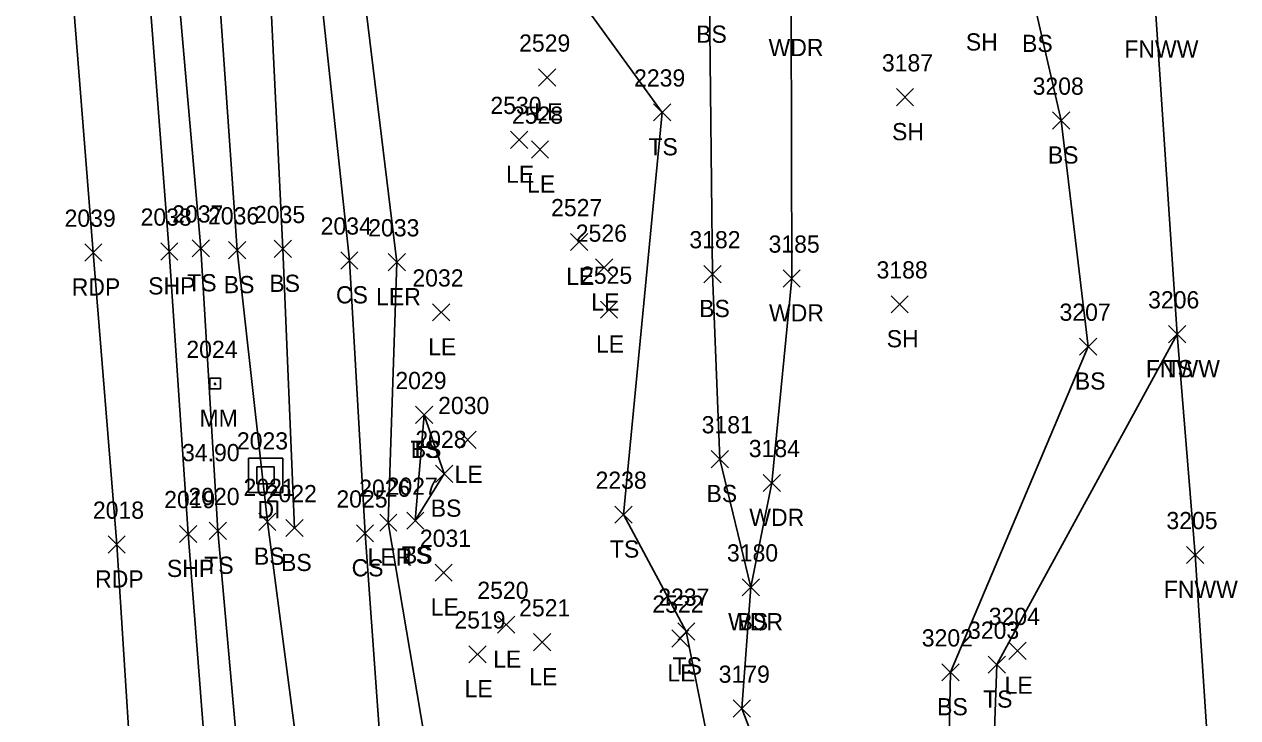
# Model space of a CAD drawing. Extents: x 1650221 to 1650634, y 244606 to 249996.
# Drawn here: x 1650407.2 to 1650548.3, y 245661.6 to 245742.3 of the extents above; entities that cross this region are included whole.
import ezdxf

# ---------------------------------------------------------------- set-up
doc = ezdxf.new("R2010")
doc.units = 0
for name, color, linetype in [('D_A', 7, 'Continuous'), ('D_I', 7, 'Continuous'), ('DS', 7, 'Continuous'), ('L_A', 7, 'Continuous'), ('L_I', 7, 'Continuous'), ('L_TIC', 7, 'Continuous'), ('LARO', 7, 'Continuous'), ('LAWA', 7, 'Continuous'), ('LELB', 7, 'Continuous'), ('LFNC', 7, 'Continuous'), ('LSOGP', 7, 'Continuous'), ('P_A', 7, 'Continuous'), ('P_I', 7, 'Continuous'), ('P_TIC', 7, 'Continuous'), ('PET', 7, 'Continuous'), ('PSP', 7, 'Continuous'), ('S_A', 7, 'Continuous'), ('S_C', 7, 'Continuous'), ('S_I', 7, 'Continuous'), ('SRM', 7, 'Continuous')]:
    doc.layers.add(name, color=color, linetype=linetype)

msp = doc.modelspace()

# ---------------------------------------------------------------- linework, layer by layer
at = {"layer": 'DS'}
for p, q in [((1650433.22, 245691.82), (1650437.22, 245691.82)), ((1650433.22, 245687.82), (1650433.22, 245691.82)), ((1650434.22, 245688.82), (1650434.22, 245690.82)), ((1650434.22, 245690.82), (1650436.22, 245690.82)), ((1650436.22, 245690.82), (1650436.22, 245688.82)), ((1650437.22, 245691.82), (1650437.22, 245687.82)), ((1650435.23, 245689.83), (1650435.23, 245689.83)), ((1650435.23, 245689.83), (1650435.23, 245689.83)), ((1650437.22, 245687.82), (1650433.22, 245687.82)), ((1650436.22, 245688.82), (1650434.22, 245688.82))]:
    msp.add_line(p, q, dxfattribs=at)
at = {"layer": 'L_TIC'}
for points in [[(1650466.98, 245735.08), (1650468.98, 245737.08)], [(1650468.98, 245735.08), (1650466.98, 245737.08)], [(1650508.59, 245732.78), (1650510.59, 245734.78)], [(1650510.59, 245732.78), (1650508.59, 245734.78)], [(1650480.34, 245731.02), (1650482.34, 245733.02)], [(1650482.34, 245731.02), (1650480.34, 245733.02)], [(1650526.76, 245730.07), (1650528.76, 245732.07)], [(1650528.76, 245730.07), (1650526.76, 245732.07)], [(1650463.72, 245727.83), (1650465.72, 245729.83)], [(1650465.72, 245727.83), (1650463.72, 245729.83)], [(1650466.14, 245726.7), (1650468.14, 245728.7)], [(1650468.14, 245726.7), (1650466.14, 245728.7)], [(1650470.69, 245715.95), (1650472.69, 245717.95)], [(1650472.69, 245715.95), (1650470.69, 245717.95)], [(1650426.7, 245715.21), (1650428.7, 245717.21)], [(1650428.7, 245715.21), (1650426.7, 245717.21)], [(1650430.92, 245715), (1650432.92, 245717)], [(1650432.92, 245715), (1650430.92, 245717)], [(1650436.22, 245715.15), (1650438.22, 245717.15)], [(1650438.22, 245715.15), (1650436.22, 245717.15)], [(1650443.97, 245713.81), (1650445.97, 245715.81)], [(1650445.97, 245713.81), (1650443.97, 245715.81)], [(1650449.49, 245713.6), (1650451.49, 245715.6)], [(1650451.49, 245713.6), (1650449.49, 245715.6)], [(1650473.61, 245712.98), (1650475.61, 245714.98)], [(1650475.61, 245712.98), (1650473.61, 245714.98)], [(1650486.21, 245712.22), (1650488.21, 245714.22)], [(1650488.21, 245712.22), (1650486.21, 245714.22)], [(1650495.41, 245711.71), (1650497.41, 245713.71)], [(1650497.41, 245711.71), (1650495.41, 245713.71)], [(1650507.97, 245708.71), (1650509.97, 245710.71)], [(1650509.97, 245708.71), (1650507.97, 245710.71)], [(1650454.64, 245707.77), (1650456.64, 245709.77)], [(1650456.64, 245707.77), (1650454.64, 245709.77)], [(1650474.17, 245708.09), (1650476.17, 245710.09)], [(1650476.17, 245708.09), (1650474.17, 245710.09)], [(1650540.25, 245705.23), (1650542.25, 245707.23)], [(1650542.25, 245705.23), (1650540.25, 245707.23)], [(1650540.25, 245705.23), (1650542.25, 245707.23)], [(1650542.25, 245705.23), (1650540.25, 245707.23)], [(1650529.9, 245703.79), (1650531.9, 245705.79)], [(1650531.9, 245703.79), (1650529.9, 245705.79)], [(1650452.67, 245695.85), (1650454.67, 245697.85)], [(1650454.67, 245695.85), (1650452.67, 245697.85)], [(1650452.67, 245695.85), (1650454.67, 245697.85)], [(1650454.67, 245695.85), (1650452.67, 245697.85)], [(1650457.72, 245692.95), (1650459.72, 245694.95)], [(1650459.72, 245692.95), (1650457.72, 245694.95)], [(1650487.06, 245690.71), (1650489.06, 245692.71)], [(1650489.06, 245690.71), (1650487.06, 245692.71)], [(1650454.99, 245689.01), (1650456.99, 245691.01)], [(1650456.99, 245689.01), (1650454.99, 245691.01)], [(1650493.11, 245687.94), (1650495.11, 245689.94)], [(1650495.11, 245687.94), (1650493.11, 245689.94)], [(1650475.86, 245684.26), (1650477.86, 245686.26)], [(1650477.86, 245684.26), (1650475.86, 245686.26)], [(1650434.43, 245683.43), (1650436.43, 245685.43)], [(1650436.43, 245683.43), (1650434.43, 245685.43)], [(1650448.5, 245683.33), (1650450.5, 245685.33)], [(1650450.5, 245683.33), (1650448.5, 245685.33)], [(1650451.64, 245683.56), (1650453.64, 245685.56)], [(1650453.64, 245683.56), (1650451.64, 245685.56)], [(1650451.64, 245683.56), (1650453.64, 245685.56)], [(1650453.64, 245683.56), (1650451.64, 245685.56)], [(1650428.68, 245682.37), (1650430.68, 245684.37)], [(1650430.68, 245682.37), (1650428.68, 245684.37)], [(1650437.58, 245682.7), (1650439.58, 245684.7)], [(1650439.58, 245682.7), (1650437.58, 245684.7)], [(1650445.79, 245682.08), (1650447.79, 245684.08)], [(1650447.79, 245682.08), (1650445.79, 245684.08)], [(1650542.33, 245679.57), (1650544.33, 245681.57)], [(1650544.33, 245679.57), (1650542.33, 245681.57)], [(1650454.94, 245677.51), (1650456.94, 245679.51)], [(1650456.94, 245677.51), (1650454.94, 245679.51)], [(1650490.66, 245675.81), (1650492.66, 245677.81)], [(1650492.66, 245675.81), (1650490.66, 245677.81)], [(1650490.66, 245675.81), (1650492.66, 245677.81)], [(1650492.66, 245675.81), (1650490.66, 245677.81)], [(1650462.2, 245671.46), (1650464.2, 245673.46)], [(1650464.2, 245671.46), (1650462.2, 245673.46)], [(1650483.15, 245670.67), (1650485.15, 245672.67)], [(1650485.15, 245670.67), (1650483.15, 245672.67)], [(1650466.4, 245669.43), (1650468.4, 245671.43)], [(1650468.4, 245669.43), (1650466.4, 245671.43)], [(1650482.46, 245669.86), (1650484.46, 245671.86)], [(1650484.46, 245669.86), (1650482.46, 245671.86)], [(1650458.88, 245668.02), (1650460.88, 245670.02)], [(1650460.88, 245668.02), (1650458.88, 245670.02)], [(1650521.67, 245668.43), (1650523.67, 245670.43)], [(1650523.67, 245668.43), (1650521.67, 245670.43)], [(1650513.88, 245665.93), (1650515.88, 245667.93)], [(1650515.88, 245665.93), (1650513.88, 245667.93)], [(1650519.26, 245666.82), (1650521.26, 245668.82)], [(1650521.26, 245666.82), (1650519.26, 245668.82)], [(1650489.62, 245661.71), (1650491.62, 245663.71)], [(1650491.62, 245661.71), (1650489.62, 245663.71)]]:
    msp.add_lwpolyline(points, dxfattribs=at)
at = {"layer": 'LARO'}
msp.add_lwpolyline([(1650458.35, 245631.93), (1650449.5, 245684.33), (1650450.49, 245714.6), (1650445.16, 245758.17), (1650441.43, 245763.32), (1650445.69, 245790.79), (1650445.26, 245833.56), (1650436.07, 245846.15), (1650437.66, 245854.86), (1650443.78, 245871.9), (1650444.44, 245931.5), (1650440.46, 245954.23), (1650431.44, 245970), (1650423.58, 246015.54), (1650425.24, 246041.2), (1650422.73, 246072.32), (1650429.42, 246092.95), (1650425.13, 246098.36), (1650427.51, 246149.08), (1650414.34, 246173.26), (1650408.62, 246217.57), (1650415.02, 246258.55)], dxfattribs=at)
at = {"layer": 'LAWA'}
msp.add_lwpolyline([(1650496.59, 245647.08), (1650490.62, 245662.71), (1650491.66, 245676.81), (1650494.11, 245688.94), (1650496.41, 245712.71), (1650496.35, 245743.56), (1650485.42, 245749.48), (1650477.6, 245752.97), (1650479.59, 245781.46), (1650478.59, 245799.8), (1650480.21, 245812.21), (1650484.49, 245828.9), (1650484.6, 245841.6), (1650491.54, 245845.62), (1650492.67, 245870.32), (1650485.54, 245895.52), (1650486.59, 245913.37), (1650488.88, 245942.33), (1650483.51, 245961.47), (1650475.64, 245986.69)], dxfattribs=at)
at = {"layer": 'LELB'}
for points in [[(1650490.9, 245637.99), (1650484.15, 245671.67), (1650476.86, 245685.26), (1650481.34, 245732.02), (1650469.96, 245747.75), (1650469.91, 245798.43), (1650476.13, 245853.71), (1650478.54, 245903.04), (1650467.9, 245956.04), (1650466.73, 245989.26), (1650462, 246035.91), (1650455.88, 246077.16), (1650453.1, 246125.91), (1650454.43, 246141.05), (1650448.02, 246165.28), (1650445.18, 246217.4), (1650445.53, 246269.3)], [(1650434.29, 245631.65), (1650429.68, 245683.37), (1650427.7, 245716.21), (1650423.74, 245761.41), (1650422.95, 245791.62), (1650419.79, 245841.04), (1650417.75, 245874.98), (1650413.21, 245925.88), (1650409.3, 245969.62), (1650405.7, 246013.51), (1650403.9, 246042.15), (1650401.96, 246074.17), (1650399.9, 246101.7), (1650397.07, 246143.43), (1650394.38, 246175.59), (1650393.27, 246215.06), (1650388.59, 246258.03)], [(1650442.32, 245632.05), (1650435.43, 245684.43), (1650431.92, 245716), (1650428.74, 245761.44), (1650429.83, 245791.58), (1650424.83, 245840.77), (1650421.85, 245874.71), (1650419.56, 245927.21), (1650413.67, 245970.03), (1650411.82, 246014.77), (1650409.82, 246042.31), (1650411.58, 246073.19), (1650407.92, 246101.42), (1650409.97, 246148.82), (1650401.75, 246175.35), (1650398.42, 246215.35), (1650393.5, 246258.25)], [(1650438.58, 245683.7), (1650437.22, 245716.15), (1650434.99, 245762.37), (1650435.62, 245791.45), (1650430.69, 245841.83), (1650429.64, 245875.08), (1650426.15, 245928.21), (1650418.7, 245970.61), (1650416.7, 246015.22), (1650413.61, 246042.18), (1650416.51, 246074.2), (1650416.4, 246101.53), (1650414.29, 246149.93), (1650404.83, 246174.67), (1650402.25, 246216.69), (1650398.47, 246258.76)], [(1650450.46, 245632.25), (1650446.79, 245683.08), (1650444.97, 245714.81), (1650439.75, 245763.7), (1650441.25, 245791.53), (1650434.82, 245844.51), (1650438.48, 245872.14), (1650441.09, 245931.18), (1650427.55, 245969.42), (1650420.96, 246016.02), (1650419.64, 246042.01), (1650419.67, 246073.52), (1650422.04, 246099.42), (1650421.43, 246149.38), (1650410.21, 246173.05), (1650406.66, 246218.25), (1650409.74, 246258.01)], [(1650521.82, 245589.88), (1650525.99, 245596.38), (1650532.14, 245604.89), (1650535.4, 245624.31), (1650529.82, 245630.33), (1650514.3, 245638.58), (1650514.88, 245666.93), (1650530.9, 245704.79), (1650527.76, 245731.07), (1650524.76, 245744.04), (1650525.69, 245770.73), (1650527.66, 245791.89), (1650535.19, 245793.78)], [(1650491.66, 245676.81), (1650488.06, 245691.71), (1650487.21, 245713.22), (1650486.86, 245745.11)], [(1650546.03, 245639.46), (1650533.89, 245639.37), (1650519.26, 245639.35), (1650520.26, 245667.82), (1650541.25, 245706.23)], [(1650452.64, 245684.56), (1650455.99, 245690.01), (1650453.67, 245696.85)], [(1650452.64, 245684.56), (1650453.67, 245696.85)]]:
    msp.add_lwpolyline(points, dxfattribs=at)
at = {"layer": 'LFNC'}
msp.add_lwpolyline([(1650546.03, 245639.46), (1650543.33, 245680.57), (1650541.25, 245706.23), (1650538.76, 245743.38), (1650537.2, 245769.33), (1650535.19, 245793.78), (1650533.98, 245796.82), (1650533.26, 245818.39), (1650530.66, 245853.72), (1650529.25, 245872.35), (1650528.02, 245888.24), (1650525.93, 245914.77), (1650524.07, 245941.51), (1650522.94, 245960.4), (1650522.45, 245965.53), (1650521.47, 245978.98)], dxfattribs=at)
at = {"layer": 'LSOGP'}
msp.add_lwpolyline([(1650546.03, 245639.46), (1650543.33, 245680.57), (1650541.25, 245706.23), (1650538.76, 245743.38), (1650537.2, 245769.33), (1650535.19, 245793.78), (1650533.98, 245796.82), (1650533.26, 245818.39), (1650530.66, 245853.72), (1650529.25, 245872.35), (1650528.02, 245888.24), (1650525.93, 245914.77), (1650524.07, 245941.51), (1650522.94, 245960.4), (1650522.45, 245965.53), (1650521.47, 245978.98)], dxfattribs=at)
at = {"layer": 'P_TIC'}
for points in [[(1650414.19, 245714.72), (1650416.19, 245716.72)], [(1650416.19, 245714.72), (1650414.19, 245716.72)], [(1650423.03, 245714.85), (1650425.03, 245716.85)], [(1650425.03, 245714.85), (1650423.03, 245716.85)], [(1650425.21, 245682.01), (1650427.21, 245684.01)], [(1650427.21, 245682.01), (1650425.21, 245684.01)], [(1650416.91, 245680.78), (1650418.91, 245682.78)], [(1650418.91, 245680.78), (1650416.91, 245682.78)]]:
    msp.add_lwpolyline(points, dxfattribs=at)
at = {"layer": 'PET'}
msp.add_lwpolyline([(1650421.18, 245630.65), (1650417.91, 245681.78), (1650415.19, 245715.72), (1650411.64, 245760.21), (1650409.56, 245790.15), (1650405.96, 245839.71), (1650403.34, 245877), (1650399.58, 245923.32), (1650396.22, 245968.53), (1650393.17, 246011.85), (1650391.12, 246041.15), (1650389.17, 246073.95), (1650387.34, 246101.09), (1650384.18, 246142.54), (1650381.86, 246175.15), (1650378.63, 246214.91), (1650375.8, 246256.56)], dxfattribs=at)
at = {"layer": 'PSP'}
msp.add_lwpolyline([(1650430.25, 245631.19), (1650426.21, 245683.01), (1650424.03, 245715.85), (1650420.58, 245760.81), (1650418.54, 245792.05), (1650414.92, 245840.84), (1650412.56, 245876.11), (1650408.95, 245925.6), (1650405.85, 245970.07), (1650402.84, 246013.32), (1650400.76, 246041.78), (1650398.21, 246073.88), (1650396.25, 246101.84), (1650393.23, 246143.04), (1650390.86, 246175.91), (1650388.25, 246215.07), (1650385.02, 246257.59)], dxfattribs=at)
at = {"layer": 'SRM'}
for p, q in [((1650430, 245701.13), (1650428.75, 245701.13)), ((1650428.75, 245701.13), (1650428.75, 245699.88)), ((1650430, 245701.13), (1650428.75, 245701.13)), ((1650428.75, 245701.13), (1650428.75, 245699.88)), ((1650430, 245699.88), (1650430, 245701.13)), ((1650430, 245699.88), (1650430, 245701.13)), ((1650428.75, 245699.88), (1650430, 245699.88)), ((1650428.75, 245699.88), (1650430, 245699.88))]:
    msp.add_line(p, q, dxfattribs=at)
msp.add_circle((1650429.35, 245700.46), 0.0833, dxfattribs=at)

# ---------------------------------------------------------------- texts
at = {"layer": 'D_A'}
msp.add_text('DI', height=2, dxfattribs=at).set_placement((1650434.28, 245684.83))
at = {"layer": 'D_I'}
msp.add_text('2023', height=2, dxfattribs=at).set_placement((1650431.89, 245692.83))
at = {"layer": 'L_A'}
for s, p in [('BS', (1650485.3, 245740.11)), ('WDR', (1650493.72, 245738.56)), ('SH', (1650516.67, 245739.21)), ('BS', (1650523.2, 245739.04)), ('FNWW', (1650535.1, 245738.38)), ('LE', (1650466.47, 245731.08)), ('SH', (1650508.08, 245728.78)), ('TS', (1650479.75, 245727.02)), ('BS', (1650526.2, 245726.07)), ('LE', (1650463.2, 245723.83)), ('LE', (1650465.63, 245722.7)), ('TS', (1650426.11, 245711.21)), ('BS', (1650435.66, 245711.15)), ('LE', (1650470.18, 245711.95)), ('BS', (1650430.36, 245711)), ('CS', (1650443.41, 245709.81)), ('LER', (1650448.08, 245709.6)), ('LE', (1650473.1, 245708.98)), ('BS', (1650485.65, 245708.22)), ('WDR', (1650493.77, 245707.71)), ('LE', (1650473.65, 245704.09)), ('SH', (1650507.46, 245704.71)), ('LE', (1650454.13, 245703.77)), ('FNWW', (1650537.6, 245701.23)), ('TS', (1650539.66, 245701.23)), ('BS', (1650529.34, 245699.79)), ('TS', (1650452.08, 245691.85)), ('BS', (1650452.11, 245691.85)), ('LE', (1650457.2, 245688.95)), ('BS', (1650486.5, 245686.71)), ('BS', (1650454.43, 245685.01)), ('WDR', (1650491.48, 245683.94)), ('TS', (1650475.27, 245680.26)), ('BS', (1650433.87, 245679.43)), ('BS', (1650437.02, 245678.7)), ('LER', (1650447.09, 245679.33)), ('TS', (1650451.05, 245679.56)), ('BS', (1650451.08, 245679.56)), ('TS', (1650428.09, 245678.37)), ('CS', (1650445.23, 245678.08)), ('FNWW', (1650539.68, 245675.57)), ('LE', (1650454.43, 245673.51)), ('WDR', (1650489.02, 245671.81)), ('BS', (1650490.1, 245671.81)), ('LE', (1650461.69, 245667.46)), ('TS', (1650482.56, 245666.67)), ('LE', (1650465.89, 245665.43)), ('LE', (1650481.95, 245665.86)), ('LE', (1650458.37, 245664.02)), ('LE', (1650521.16, 245664.43)), ('BS', (1650513.32, 245661.93)), ('TS', (1650518.67, 245662.82))]:
    msp.add_text(s, height=2, dxfattribs=at).set_placement(p)
at = {"layer": 'L_I'}
for s, p in [('2529', (1650464.71, 245739.08)), ('3187', (1650506.9, 245736.78)), ('2239', (1650478.08, 245735.02)), ('3208', (1650524.43, 245734.07)), ('2530', (1650461.37, 245731.83)), ('2528', (1650463.88, 245730.7)), ('2527', (1650468.43, 245719.95)), ('2037', (1650424.36, 245719.21)), ('2036', (1650428.53, 245719)), ('2035', (1650433.88, 245719.15)), ('2034', (1650441.63, 245717.81)), ('2033', (1650447.16, 245717.6)), ('2526', (1650471.3, 245716.98)), ('3182', (1650484.51, 245716.22)), ('3185', (1650493.72, 245715.71)), ('3188', (1650506.28, 245712.71)), ('2032', (1650452.3, 245711.77)), ('2525', (1650471.91, 245712.09)), ('3206', (1650537.86, 245709.23)), ('3206', (1650537.86, 245709.23)), ('3207', (1650527.56, 245707.79)), ('2029', (1650450.32, 245699.85)), ('2029', (1650450.32, 245699.85)), ('2030', (1650455.29, 245696.95)), ('3181', (1650485.94, 245694.71)), ('2028', (1650452.65, 245693.01)), ('3184', (1650491.42, 245691.94)), ('2021', (1650432.66, 245687.43)), ('2026', (1650446.11, 245687.33)), ('2027', (1650449.3, 245687.56)), ('2027', (1650449.3, 245687.56)), ('2238', (1650473.6, 245688.26)), ('2020', (1650426.25, 245686.37)), ('2022', (1650435.24, 245686.7)), ('2025', (1650443.46, 245686.08)), ('3205', (1650539.99, 245683.57)), ('2031', (1650453.17, 245681.51)), ('3180', (1650488.88, 245679.81)), ('3180', (1650488.88, 245679.81)), ('2520', (1650459.85, 245675.46)), ('2237', (1650480.89, 245674.67)), ('2521', (1650464.71, 245673.43)), ('2522', (1650480.2, 245673.86)), ('2519', (1650457.18, 245672.02)), ('3204', (1650519.33, 245672.43)), ('3203', (1650516.92, 245670.82)), ('3202', (1650511.54, 245669.93)), ('3179', (1650487.92, 245665.71))]:
    msp.add_text(s, height=2, dxfattribs=at).set_placement(p)
at = {"layer": 'P_A'}
for s, p in [('RDP', (1650412.68, 245710.72)), ('SHP', (1650421.57, 245710.85)), ('SHP', (1650423.75, 245678.01)), ('RDP', (1650415.4, 245676.78))]:
    msp.add_text(s, height=2, dxfattribs=at).set_placement(p)
at = {"layer": 'P_I'}
for s, p in [('2039', (1650411.85, 245718.72)), ('2038', (1650420.69, 245718.85)), ('2019', (1650423.43, 245686.01)), ('2018', (1650415.14, 245684.78))]:
    msp.add_text(s, height=2, dxfattribs=at).set_placement(p)
at = {"layer": 'S_A'}
msp.add_text('MM', height=2, dxfattribs=at).set_placement((1650427.54, 245695.47))
at = {"layer": 'S_C'}
msp.add_text('34.90', height=2, dxfattribs=at).set_placement((1650425.51, 245691.47))
at = {"layer": 'S_I'}
msp.add_text('2024', height=2, dxfattribs=at).set_placement((1650426.01, 245703.47))

doc.saveas('drawing.dxf')
